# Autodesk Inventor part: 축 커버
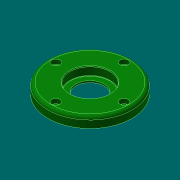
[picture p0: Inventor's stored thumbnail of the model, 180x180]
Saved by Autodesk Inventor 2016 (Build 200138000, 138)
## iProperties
Created: 2015-10
Part Number: 축 커버
Document SubType Name: Modeling
Designer: mdu
Density: 2.71 g/cm^3
Material: 알루미늄 6061
Mass: 110.828 g
Surface Area: 134.096 cm^2
Volume: 40.896 cm^3
Appearance: 진녹색
Author: mdu
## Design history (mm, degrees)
sketch "스케치1"
  geometry: C1 r 40 at (0, 0) reference; C2 r 26 at (0, 0) reference; 1 further point
  node "참조1"
  node "참조2"
extrude "돌출1" new body sketch "스케치1" distance "d0" = 10; taper "d1" = 0 deg
extrude "돌출2" join sketch "스케치1" distance "d2" = 3; taper "d3" = 0 deg
hole "구멍1" diameter "d6" = 27; stored, may be unused: countersink angle "d10" = 90 deg, drill point angle "d12" = 118 deg; dims "d7" = 6, "d8" = 38, "d9" = 8.3, "d11" = 8, "d33" = 10, "d34" = 10
sketch "스케치2"
  geometry: C1 r 20 at (0, 0); 1 further point
  constraints: 1 centre point, 1 coincident
  dimensions: "d13" = 40 diameter of C1
extrude "돌출3" cut sketch "스케치2" distance "d14" = 3; taper "d15" = 0 deg
sketch "스케치3"
  geometry: C1 r 1.621 at (0, 32.5) reference; 1 further point
hole "구멍2" sketch "스케치3" at (0, 32.5) diameter "d16" = 4.5; stored, may be unused: countersink angle "d20" = 90 deg, drill point angle "d22" = 118 deg; dims "d17" = 6, "d18" = 8, "d19" = 4.4, "d21" = 8
fillet "모깎기1" dims "d26" = 3, "d27" = 0.3
chamfer "모따기1" distance "d28" = 1; stored, may be unused: second distance "d29" = 2, angle "d30" = 45 deg
chamfer "모따기2" distance "d31" = 0.8; stored, may be unused: second distance "d32" = 2, angle "d35" = 30 deg
node "솔리드1"
pattern_circular "원형 패턴1" dims angle "d24" = 360 deg
node "참조3"
